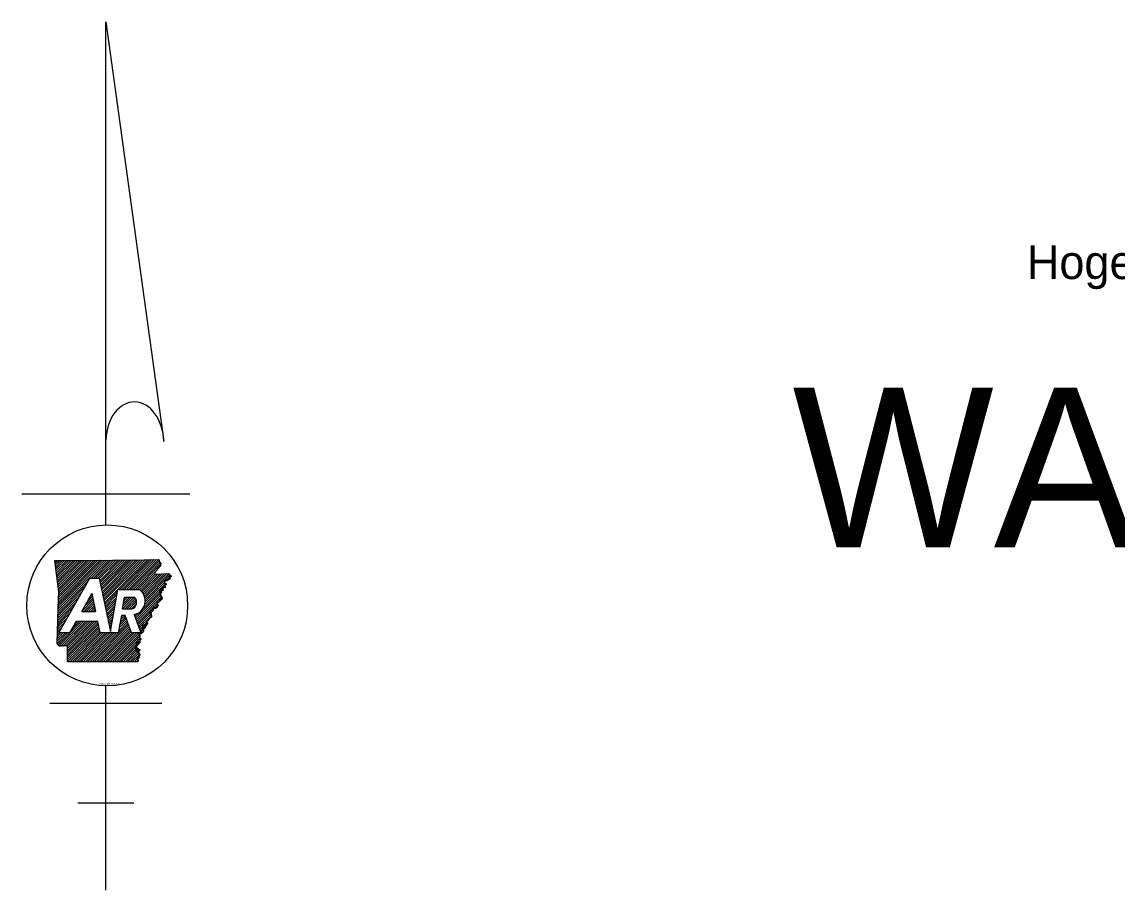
# Model space of a CAD drawing. Extents: x 31699 to 244310, y -8841 to 11474.
# Drawn here: x 98042 to 101474, y -1421 to 1299 of the extents above; entities that cross this region are included whole.
import ezdxf

# ---------------------------------------------------------------- set-up
doc = ezdxf.new("R2010")
doc.units = 0
for name, color, linetype in [('G-ANNO-SYMB', 7, 'Continuous'), ('Level 48', 7, 'Continuous'), ('R_Border', 7, 'Continuous')]:
    doc.layers.add(name, color=color, linetype=linetype)

msp = doc.modelspace()

# ---------------------------------------------------------------- linework, layer by layer
at = {"layer": 'Level 48'}
for p, q in [((98305.1, 1299), (98486.9, -15.1)), ((98305.1, -276.8), (98305.1, 1299)), ((98041.9, -179.4), (98568.2, -179.4)), ((98145.4, -389.7), (98147.6, -387.6)), ((98146.2, -395.9), (98154.5, -387.6)), ((98146.9, -402.1), (98161.5, -387.6)), ((98147.7, -408.3), (98168.5, -387.6)), ((98148.5, -414.5), (98175.4, -387.6)), ((98149.3, -420.7), (98182.4, -387.6)), ((98150, -426.9), (98189.3, -387.6)), ((98150.8, -433.1), (98196.3, -387.6)), ((98151.6, -439.3), (98203.3, -387.6)), ((98152.3, -445.5), (98210.2, -387.6)), ((98153.1, -451.7), (98217.2, -387.6)), ((98153.9, -457.9), (98224.1, -387.6)), ((98154.7, -464.1), (98231.1, -387.6)), ((98155.4, -470.3), (98238.1, -387.6)), ((98155.7, -539.7), (98307.9, -387.5)), ((98155.9, -532.5), (98300.9, -387.5)), ((98156.1, -525.3), (98293.9, -387.5)), ((98156.2, -476.5), (98245, -387.6)), ((98156.4, -518.1), (98286.9, -387.5)), ((98156.6, -510.9), (98279.9, -387.5)), ((98156.9, -503.7), (98273, -387.6)), ((98157, -482.6), (98252, -387.6)), ((98157.1, -496.5), (98266, -387.6)), ((98157.3, -489.3), (98259, -387.6)), ((98259.1, -443.2), (98314.8, -387.5)), ((98266.1, -443.2), (98321.8, -387.5)), ((98273, -443.2), (98328.9, -387.4)), ((98280, -443.2), (98335.9, -387.3)), ((98284.3, -445.8), (98343, -387.2)), ((98285.6, -451.6), (98350.1, -387.1)), ((98286.8, -457.3), (98357.2, -387)), ((98288, -463), (98364.2, -386.8)), ((98289.2, -468.8), (98371.3, -386.7)), ((98290.5, -474.5), (98378.4, -386.6)), ((98291.7, -480.3), (98385.5, -386.5)), ((98292.9, -486), (98392.5, -386.4)), ((98294.2, -491.7), (98399.6, -386.3)), ((98295.4, -497.5), (98406.7, -386.2)), ((98296.6, -503.2), (98413.8, -386.1)), ((98297.8, -509), (98420.8, -386)), ((98299.1, -514.7), (98427.9, -385.8)), ((98300.3, -520.4), (98435.1, -385.7)), ((98348.7, -479), (98442.2, -385.5)), ((98355.7, -479), (98449.3, -385.3)), ((98362.6, -479), (98456.5, -385.2)), ((98369.6, -479), (98463.6, -385)), ((98376.6, -479), (98470.7, -384.8)), ((98383.5, -479), (98472.3, -390.3)), ((98390.5, -479), (98475.6, -393.9)), ((98397.5, -479), (98476.5, -399.9)), ((98157.7, -614.8), (98254.9, -443.2)), ((98254.9, -443.2), (98283.8, -443.2)), ((98404.4, -479), (98460.6, -422.8)), ((98410.7, -479.6), (98459.3, -431.1)), ((98414.5, -482.8), (98466.6, -430.7)), ((98417.9, -486.4), (98474, -430.4)), ((98421, -490.3), (98481.3, -430)), ((98423.5, -494.7), (98488.6, -429.6)), ((98425.7, -499.5), (98496, -429.2)), ((98427.3, -504.9), (98502.6, -429.6)), ((98428.2, -510.9), (98505.8, -433.3)), ((98502.8, -443.4), (98509.1, -437)), ((98155.2, -554.1), (98240.3, -469)), ((98155.4, -546.9), (98249.4, -452.9)), ((98342.4, -479), (98409.9, -479)), ((98426.8, -526.3), (98490, -463.1)), ((98428.3, -517.9), (98489.2, -456.9)), ((98482.2, -477.8), (98490.8, -469.2)), ((98154.7, -568.5), (98222.1, -501.1)), ((98154.9, -561.3), (98231.2, -485)), ((98229.2, -547.5), (98261, -491.3)), ((98229.5, -547.5), (98265.3, -511.7)), ((98237.9, -532.2), (98264.1, -505.9)), ((98247, -516.1), (98262.9, -500.2)), ((98256.1, -500.1), (98261.7, -494.4)), ((98301.5, -526.2), (98341.1, -486.6)), ((98302.8, -531.9), (98339.6, -495.1)), ((98304, -537.6), (98338.1, -503.5)), ((98305.2, -543.4), (98336.6, -511.9)), ((98357.1, -539.9), (98393.7, -503.2)), ((98358.5, -531.5), (98386.8, -503.2)), ((98360, -523), (98379.8, -503.2)), ((98361.4, -514.6), (98372.8, -503.2)), ((98362.9, -506.2), (98365.9, -503.2)), ((98363.4, -503.2), (98395.1, -503.2)), ((98364, -539.9), (98397.6, -506.3)), ((98371, -539.9), (98399.9, -510.9)), ((98398, -569), (98475.3, -491.7)), ((98399.9, -574.1), (98476.6, -497.4)), ((98401.8, -579.1), (98477.9, -503.1)), ((98403.7, -584.2), (98479.2, -508.7)), ((98420.7, -539.3), (98474, -486.1)), ((98154.2, -582.9), (98203.9, -533.2)), ((98154.5, -575.7), (98213, -517.1)), ((98229.2, -547.5), (98273, -547.5)), ((98236.5, -547.5), (98266.6, -517.4)), ((98243.5, -547.5), (98267.8, -523.1)), ((98250.4, -547.5), (98269, -528.9)), ((98257.4, -547.5), (98270.3, -534.6)), ((98264.4, -547.5), (98271.5, -540.3)), ((98271.3, -547.5), (98272.7, -546.1)), ((98306.4, -549.1), (98335.2, -520.4)), ((98307.7, -554.9), (98333.7, -528.8)), ((98308.9, -560.6), (98332.2, -537.3)), ((98310.1, -566.3), (98330.8, -545.7)), ((98357, -539.9), (98386, -539.9)), ((98378, -539.9), (98401.2, -516.6)), ((98384.9, -539.9), (98400.6, -524.2)), ((98405.6, -589.3), (98447.3, -547.5)), ((98455.4, -539.5), (98465.1, -529.7)), ((98153.5, -604.5), (98176.7, -581.4)), ((98153.7, -597.3), (98185.8, -565.3)), ((98154, -590.1), (98194.9, -549.2)), ((98154.8, -652), (98228, -578.8)), ((98158.9, -654.8), (98235, -578.8)), ((98163.9, -656.8), (98241.9, -578.8)), ((98172.2, -655.5), (98248.9, -578.8)), ((98179.3, -655.4), (98255.9, -578.8)), ((98184.7, -656.9), (98262.8, -578.8)), ((98185, -670.6), (98276.8, -578.8)), ((98185, -663.6), (98269.8, -578.8)), ((98185, -677.5), (98280.4, -582.1)), ((98211.5, -578.8), (98191.1, -614.8)), ((98199, -600.9), (98221, -578.8)), ((98208.1, -584.8), (98214.1, -578.8)), ((98279.7, -578.8), (98211.5, -578.8)), ((98311.4, -572.1), (98329.3, -554.1)), ((98312.6, -577.8), (98327.8, -562.6)), ((98313.8, -583.5), (98326.4, -571)), ((98315, -589.3), (98324.9, -579.4)), ((98345.2, -607.9), (98372.6, -580.4)), ((98346.6, -599.5), (98370.8, -575.4)), ((98348.1, -591), (98368.9, -570.3)), ((98349.6, -582.6), (98367, -565.2)), ((98351.1, -574.2), (98365, -560.2)), ((98352.5, -565.7), (98358, -560.2)), ((98365.2, -560.2), (98353.5, -560.2)), ((98385.3, -614.8), (98365.2, -560.2)), ((98393.7, -557.3), (98415, -614.8)), ((98394.3, -558.8), (98396.4, -556.7)), ((98396.2, -563.9), (98409.4, -550.6)), ((98407.4, -594.4), (98446.6, -555.3)), ((98409.3, -599.5), (98445.8, -563)), ((98411.2, -604.6), (98432.6, -583.2)), ((98152.2, -647.6), (98185, -614.8)), ((98152.3, -640.5), (98178.1, -614.8)), ((98152.6, -633.3), (98171.1, -614.8)), ((98152.8, -626.1), (98164.1, -614.8)), ((98153, -618.9), (98158.5, -613.5)), ((98153.3, -611.7), (98167.6, -597.4)), ((98191.1, -614.8), (98157.7, -614.8)), ((98185, -684.5), (98281.6, -587.8)), ((98185, -691.4), (98282.9, -593.6)), ((98185, -698.4), (98284.1, -599.3)), ((98185.2, -705.2), (98285.3, -605.1)), ((98192.1, -705.2), (98286.6, -610.8)), ((98199.1, -705.2), (98289.5, -614.8)), ((98206, -705.3), (98296.5, -614.8)), ((98213, -705.3), (98303.4, -614.8)), ((98219.9, -705.3), (98310.4, -614.8)), ((98226.9, -705.3), (98317.4, -614.8)), ((98233.8, -705.3), (98324.3, -614.8)), ((98240.8, -705.3), (98331.3, -614.8)), ((98247.8, -705.3), (98338.3, -614.8)), ((98254.7, -705.3), (98374.5, -585.5)), ((98261.7, -705.3), (98376.4, -590.6)), ((98268.6, -705.4), (98378.3, -595.7)), ((98275.6, -705.4), (98380.2, -600.8)), ((98282.5, -705.4), (98382, -605.9)), ((98344, -614.8), (98287.4, -614.8)), ((98289.5, -705.4), (98383.9, -611)), ((98296.4, -705.4), (98387, -614.8)), ((98303.4, -705.4), (98394, -614.8)), ((98310.3, -705.4), (98401, -614.8)), ((98316.3, -595), (98323.4, -587.9)), ((98317.3, -705.4), (98407.9, -614.8)), ((98317.5, -600.8), (98321.9, -596.3)), ((98318.7, -606.5), (98320.5, -604.7)), ((98415, -614.8), (98385.3, -614.8)), ((98413.1, -609.7), (98429.6, -593.2)), ((98324.3, -705.4), (98410.3, -619.4)), ((98331.2, -705.5), (98410.6, -626.1)), ((98338.2, -705.5), (98410.9, -632.8)), ((98345.1, -705.5), (98411.2, -639.4)), ((98352.1, -705.5), (98399.7, -657.8)), ((98359, -705.5), (98401.9, -662.6)), ((98366, -705.5), (98404, -667.4)), ((98372.9, -705.5), (98406.2, -672.3)), ((98379.9, -705.5), (98408.3, -677.1)), ((98386.8, -705.5), (98410.1, -682.2)), ((98393.8, -705.6), (98407, -692.4)), ((98400.8, -705.6), (98403.8, -702.5)), ((98305.1, -1420.5), (98305.1, -780.9)), ((98129.6, -835.3), (98480.5, -835.3)), ((98217.3, -1146.9), (98392.8, -1146.9))]:
    msp.add_line(p, q, dxfattribs=at)
for points in [[(98145.1, -387.6), (98241.2, -387.6), (98325.6, -387.4), (98425.1, -385.9), (98471.2, -384.8)], [(98145.1, -387.6), (98241.2, -387.6), (98325.6, -387.4), (98425, -385.9), (98471.2, -384.8)], [(98155.7, -537), (98157.4, -486.3), (98145.1, -387.6)], [(98152.1, -647.6), (98157.4, -486.3), (98145.1, -387.6)], [(98283.8, -443.2), (98319.5, -610.2), (98342.4, -479)], [(98501.4, -429), (98509.7, -437.7), (98488.9, -454.7), (98491.2, -471.9), (98473.4, -483.6), (98479.5, -510.1), (98465.8, -522.6), (98464.6, -536.2), (98447.9, -542.2), (98445.3, -567.8), (98433.3, -580.7), (98427.5, -600), (98410.1, -615.9), (98411.4, -644.1), (98399.6, -657.4), (98410.4, -681.6), (98402.9, -705.6)], [(98456.9, -431.2), (98502, -428.9)], [(98456.9, -431.2), (98502, -428.9)], [(98261, -491.3), (98273, -547.5)], [(98357, -539.9), (98363.4, -503.2)], [(98152.1, -647.6), (98155.7, -537)], [(98287.4, -614.8), (98279.7, -578.8)], [(98353.5, -560.2), (98344, -614.8)], [(98402.9, -705.6), (98185.1, -705.2), (98184.9, -657.1)], [(98402.9, -705.6), (98185.1, -705.2), (98185, -657.1)]]:
    msp.add_lwpolyline(points, dxfattribs=at)
for centre, major_axis, ratio, start_param, end_param in [((98395.9, -17.9), (-3.9, 126.3), 0.719778, 4.712385, 7.768526), ((98384.8, -514.7), (-43.6, 0), 0.999987, 1.777838, 4.099264), ((98379, -518.7), (-22.3, 0), 0.999987, 1.887169, 3.90762)]:
    msp.add_ellipse(centre, major_axis=major_axis, ratio=ratio, start_param=start_param, end_param=end_param, dxfattribs=at)
msp.add_ellipse((98309.2, -528.9), major_axis=(252.1, 0), ratio=0.999976, dxfattribs=at)
for points in [[(98471.2, -384.8), (98471.5, -387.4), (98472.3, -388.8), (98472.4, -391.3), (98473.4, -392.4), (98475.2, -393.5), (98476.7, -395.2), (98477, -397.2), (98476.6, -399.2), (98476.4, -401.6), (98476.2, -403.6), (98475.8, -405.4), (98474.4, -406.9), (98473.1, -408), (98471.8, -409.2), (98470.9, -410.6), (98469.4, -412), (98467.8, -413.5), (98466.5, -414.8), (98465.3, -416.4), (98464.7, -418.3), (98463.4, -419.6), (98462.3, -420.8), (98460.9, -422.4), (98460.2, -424), (98458.8, -425.8), (98458.5, -427.6), (98457.6, -429), (98457.5, -429.3)], [(98471.2, -384.8), (98471.5, -387.4), (98472.3, -388.8), (98472.4, -391.3), (98473.4, -392.4), (98475.1, -393.4), (98476.7, -395.2), (98477, -397.2), (98476.6, -399.3), (98476.5, -401.6), (98476.2, -403.6), (98475.9, -405.4), (98474.4, -406.9), (98473.1, -408), (98471.8, -409.3), (98470.9, -410.6), (98469.4, -412), (98467.8, -413.5), (98466.6, -414.8), (98465.3, -416.4), (98464.7, -418.3), (98463.4, -419.6), (98462.3, -420.8), (98460.9, -422.4), (98460.2, -424), (98458.8, -425.8), (98458.5, -427.6), (98457.6, -429), (98457.6, -429.3)], [(98501.4, -429), (98502, -428.9), (98504, -431), (98504.9, -432.9), (98506.2, -433.8), (98507.7, -434.4), (98508.8, -435.8), (98509.6, -437.3), (98509.2, -438.6), (98507.5, -438.7), (98505.7, -439), (98503.9, -438.9), (98502.5, -440.1), (98503.8, -441.7), (98505.5, -443.2), (98506, -444.8), (98505, -446.3), (98503.1, -447.2), (98501.3, -447.9), (98499.6, -449.3), (98498.8, -450.7), (98497, -451.3), (98495.1, -451.8), (98493.5, -452), (98491.6, -452.4), (98489.7, -453.3), (98488.9, -454.8), (98489.2, -457), (98489.1, -459.3), (98491.1, -460.1), (98492.8, -460.1), (98494.5, -461), (98494.3, -462.3), (98493, -464), (98491.6, -465.3), (98490.1, -465.9), (98488.7, -467.2), (98489.2, -468.5), (98490.4, -469.3), (98491.3, -470.6), (98491.2, -471.9), (98489.8, -472.8), (98488.2, -472.4), (98487.1, -470.9), (98485.8, -470.5), (98484.6, -469.9), (98483.3, -470.7), (98483.3, -472.4), (98482.9, -474.2), (98483.3, -475.6), (98483.8, -477.5), (98483.7, -478.9), (98483.3, -481), (98482.3, -483.1), (98481.1, -483.7), (98480.6, -481.5), (98480.4, -479.6), (98479.6, -478.5), (98478.7, -478.5), (98477.5, -479.4), (98476.1, -480.8), (98474.4, -482.2), (98473.4, -483.7), (98473.9, -485.5), (98475.2, -486), (98476.2, -485.7), (98476.8, -484.5), (98477.7, -484.3), (98478.7, -486.2)], [(98478.7, -486.2), (98479, -487.9), (98478, -489.7), (98477.6, -491.5), (98477.7, -493.4), (98475.8, -494.4), (98474.2, -495.6), (98475.2, -497), (98477, -498.3), (98478.7, -499.3), (98479.8, -500.4), (98480.1, -502.8), (98480.4, -504.3), (98481.1, -506.5), (98481.3, -508), (98480.2, -509.7), (98479, -510.1), (98477.6, -509.7), (98476.1, -509.6), (98474.9, -510.7), (98474, -512.4), (98473.1, -514.1), (98472.4, -515.5), (98471.7, -517.1), (98470.5, -518.9), (98468.9, -519.1), (98466.9, -519.6), (98465.8, -520.9), (98466, -523.1), (98467.1, -524.6), (98467.9, -526.4), (98468.5, -528), (98468.2, -530.1), (98467.4, -531.6), (98466.3, -532.5), (98465.8, -534.3), (98465, -535.8), (98464.3, -536.3), (98462.9, -536.1), (98461.4, -535.9), (98460.1, -536), (98458.8, -536.6), (98457.5, -536.2), (98456.2, -534.8), (98455.2, -533.7), (98454, -533.3), (98452.7, -533.9), (98452.5, -535.9), (98453.1, -537.9), (98453.6, -540.6), (98453.1, -542.3), (98452.9, -545.1)], [(98452.9, -545.1), (98450.8, -546.6), (98449.9, -548.3), (98444.6, -547.8), (98444.8, -549.7), (98442.9, -550.6), (98441.2, -551.8), (98442.2, -553.3), (98444, -554.6), (98445.7, -555.6), (98446.9, -556.6), (98447.1, -559.1), (98447.5, -560.6), (98448.1, -562.8), (98448.3, -564.2), (98447.2, -566), (98446, -566.3), (98444.7, -565.9), (98443.1, -565.8), (98441.9, -567), (98441, -568.7), (98440.1, -570.4), (98439.4, -571.8), (98438.7, -573.3), (98437.5, -575.1), (98435.9, -575.4), (98434, -575.9), (98432.8, -577.1), (98433, -579.4), (98434.1, -580.8), (98434.9, -582.7), (98435.5, -584.3), (98435.3, -586.3), (98434.4, -587.8), (98433.3, -588.7), (98432.8, -590.6), (98432.1, -592), (98431.4, -592.5), (98429.9, -592.3), (98428.4, -592.1), (98427.1, -592.2), (98425.9, -592.9), (98424.6, -592.4), (98423.3, -591), (98422.2, -589.9), (98421, -589.5), (98419.7, -590.2), (98419.6, -592.2), (98420.2, -594.1), (98420.7, -596.9), (98420.2, -598.5), (98420, -601.3)], [(98420, -601.3), (98419.8, -601.4), (98418.8, -602.7), (98419.3, -604.8), (98421.7, -605.7), (98422.7, -607.7), (98422.8, -609.4), (98422, -611.9), (98420.9, -613), (98418.9, -613.5), (98417.3, -613.8), (98417, -616.5), (98416.3, -617.9), (98415.1, -618.3), (98413.3, -617.4), (98412.2, -617), (98410.9, -616.4), (98409.2, -615.5), (98408, -615.6), (98408.3, -618.2), (98408.5, -618.3), (98409.9, -620.3), (98411.3, -621.8), (98411.9, -623.7)], [(98420, -601.3), (98419.8, -601.4), (98418.8, -602.7), (98419.3, -604.8), (98421.7, -605.7), (98422.7, -607.7), (98422.8, -609.4), (98422, -611.9), (98420.9, -613), (98418.9, -613.5), (98417.3, -613.8), (98417, -616.5), (98416.3, -617.9), (98415.1, -618.3), (98413.3, -617.4), (98412.2, -617), (98410.9, -616.4), (98409.2, -615.5), (98408, -615.6), (98408.3, -618.2), (98408.5, -618.3), (98409.9, -620.3), (98411.3, -621.8), (98411.9, -623.7)], [(98185, -657.1), (98185.2, -657.2), (98184.1, -656.5), (98182.5, -655.7), (98180.8, -655.6), (98178.6, -655.3), (98176.7, -655.1), (98174.9, -653.9), (98172.8, -655.1), (98170.6, -656.1), (98169.3, -655), (98167.6, -655.8), (98166.3, -655.4), (98164.3, -656.8), (98162.3, -656.3), (98160.9, -656.7), (98159.1, -656.7), (98158.7, -654.6), (98157, -654.4), (98155.5, -653.5), (98154.5, -651.5), (98153.8, -649.8), (98152.1, -647.6)], [(98184.9, -657.1), (98185.2, -657.3), (98184.1, -656.5), (98182.5, -655.7), (98180.8, -655.6), (98178.6, -655.3), (98176.7, -655.1), (98174.8, -653.9), (98172.8, -655.2), (98170.6, -656.1), (98169.3, -655.1), (98167.5, -655.8), (98166.3, -655.4), (98164.3, -656.8), (98162.3, -656.3), (98160.9, -656.7), (98159.1, -656.7), (98158.7, -654.6), (98157, -654.3), (98155.5, -653.5), (98154.5, -651.4), (98153.8, -649.8), (98152.1, -647.6)], [(98411.9, -623.7), (98411.4, -625.1), (98410.7, -627.4), (98410.9, -629.4), (98411.8, -631.1), (98413.2, -632.1), (98414.8, -633.5), (98414.7, -635.6), (98413.7, -636.3), (98411.6, -635.8), (98410, -635.1), (98408.7, -635.5), (98406.9, -636.4), (98405.5, -636.6), (98405.6, -639.4), (98407.4, -641.5), (98409, -641.5), (98410.9, -641.7), (98411.5, -643.8), (98410.4, -645.6), (98408.7, -646.5), (98406.4, -645.4), (98404.8, -644.3), (98403.2, -643.2), (98401.2, -642.7), (98400, -642.9), (98399.5, -645.4), (98400.4, -647.7), (98402, -649.2), (98403.4, -651.2), (98403.2, -652.8), (98402.1, -653.1), (98400.2, -653.6), (98399.1, -654.1), (98398.8, -654.6), (98399.4, -656.7), (98399.9, -658.8), (98399.9, -660.5), (98399.2, -662), (98398.2, -664.4), (98398.4, -665.9), (98399.1, -666.7), (98400, -666.5), (98401.2, -665.6), (98401.9, -664.7), (98402.6, -663.5), (98403.8, -662.5), (98405.4, -663.4), (98405.7, -665.2), (98404.8, -666.8), (98403.6, -667.6), (98402.1, -668.2), (98400.9, -669.4), (98401.2, -671), (98402.1, -671.8), (98404.3, -671.4), (98405.8, -670.7), (98406.6, -670), (98407.6, -668.9), (98408.1, -667.9), (98408.9, -666.8), (98410.3, -666.5), (98411, -667.4), (98410.7, -669.4), (98409.9, -671.4), (98408.7, -672.9), (98407.5, -674.1), (98406, -676.5), (98406.3, -678.7), (98406.9, -680.6), (98407.7, -682), (98409.1, -681.8), (98410.7, -681.6), (98411.6, -682.3), (98411.6, -684), (98410.4, -685.6), (98409.2, -687.2), (98408.7, -689.3), (98408.9, -690.8), (98408.9, -692.1), (98408.4, -693.6), (98407.6, -694.5), (98405.4, -694.4), (98403.1, -694.2), (98401.8, -694.9), (98402.1, -696.9), (98403.4, -698.4), (98404.3, -699.1), (98405.7, -700.8), (98406.3, -702.2), (98406.1, -703.4), (98405.3, -704.4), (98402.9, -705.6)], [(98411.9, -623.7), (98411.4, -625.1), (98410.7, -627.4), (98410.9, -629.4), (98411.8, -631.1), (98413.2, -632.1), (98414.8, -633.5), (98414.7, -635.6), (98413.7, -636.3), (98411.6, -635.8), (98410, -635.1), (98408.7, -635.5), (98406.9, -636.4), (98405.5, -636.6), (98405.6, -639.4), (98407.4, -641.5), (98409, -641.5), (98410.9, -641.7), (98411.5, -643.8), (98410.4, -645.6), (98408.7, -646.5), (98406.4, -645.4), (98404.8, -644.3), (98403.2, -643.2), (98401.2, -642.7), (98400, -642.9), (98399.5, -645.4), (98400.4, -647.7), (98402, -649.2), (98403.4, -651.2), (98403.2, -652.8), (98402.1, -653.1), (98400.2, -653.6), (98399.1, -654.1), (98398.8, -654.6), (98399.4, -656.7), (98399.9, -658.8), (98399.9, -660.5), (98399.2, -662), (98398.2, -664.4), (98398.4, -665.9), (98399.1, -666.7), (98400, -666.5), (98401.2, -665.6), (98401.9, -664.7), (98402.6, -663.5), (98403.8, -662.5), (98405.4, -663.4), (98405.7, -665.2), (98404.8, -666.8), (98403.6, -667.6), (98402.1, -668.2), (98400.9, -669.4), (98401.2, -671), (98402.1, -671.8), (98404.3, -671.4), (98405.8, -670.7), (98406.6, -670), (98407.6, -668.9), (98408.1, -667.9), (98408.9, -666.8), (98410.3, -666.5), (98411, -667.4), (98410.7, -669.4), (98409.9, -671.4), (98408.7, -672.9), (98407.5, -674.1), (98406, -676.5), (98406.3, -678.7), (98406.9, -680.6), (98407.7, -682), (98409.1, -681.8), (98410.7, -681.6), (98411.6, -682.3), (98411.6, -684), (98410.4, -685.6), (98409.2, -687.2), (98408.7, -689.3), (98408.9, -690.8), (98408.9, -692.1), (98408.4, -693.6), (98407.6, -694.5), (98405.4, -694.4), (98403.1, -694.2), (98401.8, -694.9), (98402.1, -696.9), (98403.4, -698.4), (98404.3, -699.1), (98405.7, -700.8), (98406.3, -702.2), (98406.1, -703.4), (98405.3, -704.4), (98402.9, -705.6)]]:
    msp.add_spline(points, degree=3, dxfattribs=at)

# ---------------------------------------------------------------- texts
at = {"layer": 'G-ANNO-SYMB'}
msp.add_text('Hogeye', height=105.6, dxfattribs=at).set_placement((101191, 493.5))
at = {"layer": 'Level 48'}
msp.add_text('STS 10-03-17', height=7.288, dxfattribs=at).set_placement((98285, -778.9))
at = {"layer": 'R_Border'}
msp.add_text('WASHINGTON', height=500, dxfattribs=at).set_placement((100456.4, -346.5))

doc.saveas('drawing.dxf')
